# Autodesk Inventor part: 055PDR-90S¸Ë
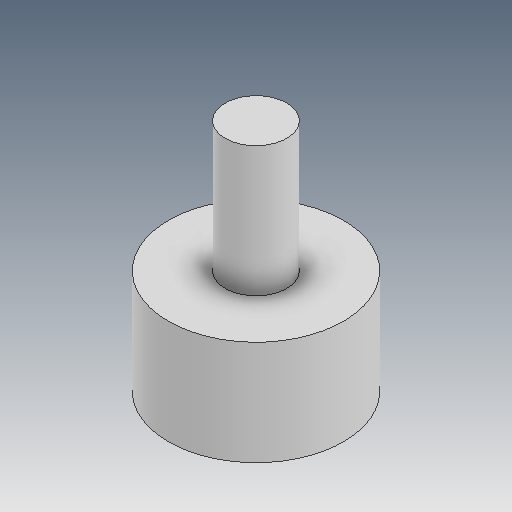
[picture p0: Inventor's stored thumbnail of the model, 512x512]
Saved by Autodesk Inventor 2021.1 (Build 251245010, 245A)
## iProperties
Created: 2019-04
Part Number: 055PDR-90S¸Ë
Material: Ogólny
Document SubType Name: Modeling
Designer: user
Density: 1 g/cm^3
Appearance: Domyślna
Author: user
Revision Number: ÈÎºÎ
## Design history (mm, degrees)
feature "Ðý×ª1"
node "Bryła1"
